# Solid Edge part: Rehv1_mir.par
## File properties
Author: KULL
Template: Iso Metric Part.par
Last saved by: KULL
Revision: 2
Application: Solid Edge
Accuracy: 0,990
Username: KULL
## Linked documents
Rehv1.par
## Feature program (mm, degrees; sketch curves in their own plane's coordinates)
part copy "CopiedPart_1"
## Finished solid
Body 1: solid body, 650 faces, 1688 edges, 1040 vertices.
  Faces by surface: spline 520, torus 62, cylinder 54, cone 8, plane 6
  Edges by curve: intersection 1040, line 390, curve on surface 130, circle 128
Bounding box of the edges (mm; curved faces can reach further): 42.451 x 100.967 x 100.966, from (-41.2257, -50.4835, -50.483) to (1.2257, 50.4835, 50.483).
Cylindrical faces by radius (mm): R49.482 x1, R50.082 x52, R50.482 x1
Conical faces (half-angle, radius in mm at the cone's reference point): 14.1898 deg R43.1591 x1, 14.1898 deg R43.6493 x1, 14.1898 deg R44.4434 x1, 14.1898 deg R44.864 x1, 75.8102 deg R41.5194 x1, 75.8102 deg R41.7645 x1, 75.8102 deg R43.6493 x1, 75.8102 deg R44.864 x1
Toroidal faces (ring radius, tube radius in mm): R41.9116 r0.6 x2, R41.9116 r1.6 x2, R43.4159 r0.2 x2, R47.1178 r2.3642 x2, R47.1178 r2.9642 x52, R47.1178 r3.3642 x2
Planar faces by outward normal: +x 3, -x 3
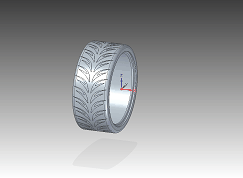
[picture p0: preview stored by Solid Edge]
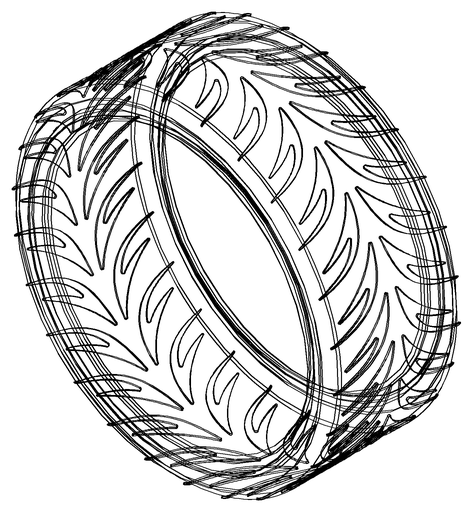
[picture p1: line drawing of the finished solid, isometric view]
